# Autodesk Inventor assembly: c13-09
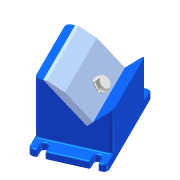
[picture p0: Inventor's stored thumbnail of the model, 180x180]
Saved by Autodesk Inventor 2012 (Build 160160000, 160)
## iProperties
Created: 2010-11
Part Number: c13-09
Document SubType Name: Assembly
Designer: Beta-8540w
Author: Beta-8540w
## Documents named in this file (5)
- C:\Users\VMuser\Desktop\Inventor 2012 Essentials\Assemblies\Chapter 13\c13-09.iam
- C:\Users\VMuser\Desktop\Inventor 2012 Essentials\Content Center Files\en-US\ISO 4017\ISO 4017 - M10 x 35ISO.ipt
- C:\Users\VMuser\Desktop\Inventor 2012 Essentials\Parts\Chapter 13\c13-02.ipt
- C:\Users\VMuser\Desktop\Inventor 2012 Essentials\Content Center Files\en-US\ISO 7091\ISO 7091 - ST 10 - 100 HV.ipt
- C:\Users\VMuser\Desktop\Inventor 2012 Essentials\Parts\Chapter 13\c13-01.ipt
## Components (4 placed, 4 different names)
1. c13-01:1 — Insert:1, Angle:1
2. c13-02:1 — Insert:1, Angle:1, Insert:2
3. ISO 4017 M10 x 35:1 — Insert:3, Bolt Angle
4. ISO 7091 ST 10 - 100 HV:1 — Insert:2, Insert:3
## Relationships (5: Insert 3, Angle 2)
- Insert:1: c13-01:1 ↔ c13-02:1
- Angle:1: c13-01:1 ↔ c13-02:1
- Insert:2: c13-02:1 ↔ ISO 7091 ST 10 - 100 HV:1
- Insert:3: ISO 4017 M10 x 35:1 ↔ ISO 7091 ST 10 - 100 HV:1
- Bolt Angle [Angle]: ISO 4017 M10 x 35:1
